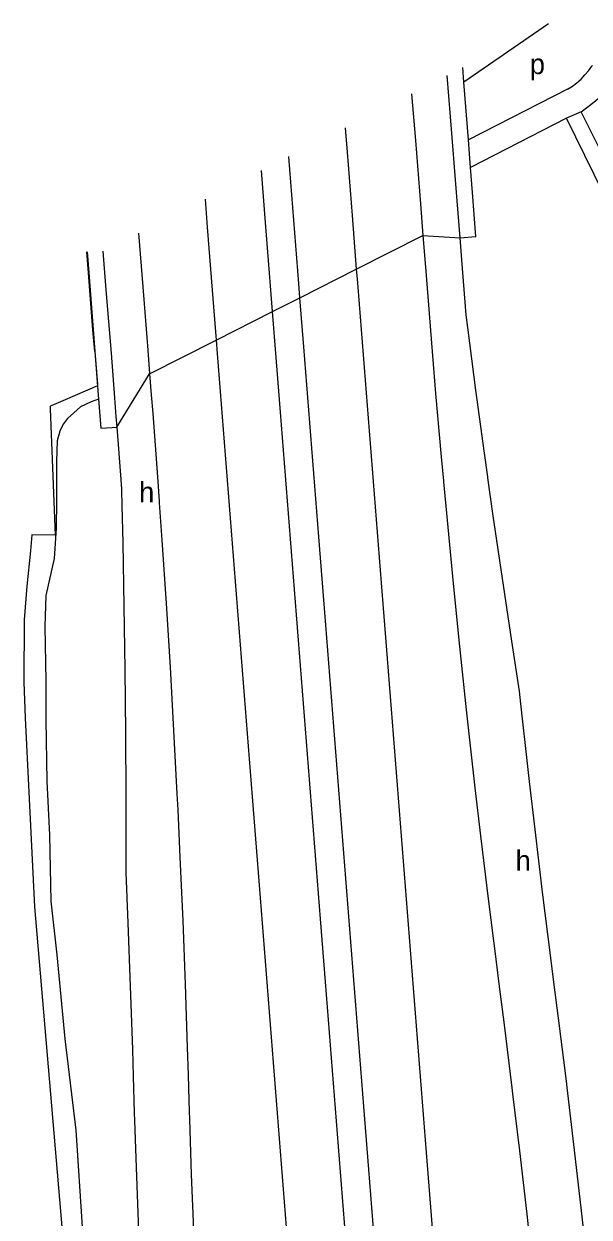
# Model space of a CAD drawing. Extents: x 157794 to 159375, y 380877 to 382306.
# Drawn here: x 157819.1 to 157930.4, y 381260.8 to 381495.7 of the extents above; entities that cross this region are included whole.
import ezdxf

# ---------------------------------------------------------------- set-up
doc = ezdxf.new("R2010")
doc.units = 0
for name, color, linetype in [('BLT_Basislijn', 7, 'Continuous'), ('BLT_Centroide', 7, 'Continuous'), ('BLT_Gemeentegrens', 7, 'Continuous'), ('BLT_Vlakafsluiter', 7, 'Continuous')]:
    doc.layers.add(name, color=color, linetype=linetype)

msp = doc.modelspace()

# ---------------------------------------------------------------- linework, layer by layer
at = {"layer": 'BLT_Basislijn'}
for p, q in [((157926.16, 381482.84), (157906.62, 381472.85)), ((157928.82, 381478.37), (157925.97, 381477.12)), ((157941.55, 381452.87), (157928.82, 381478.37)), ((157925.97, 381477.12), (157907.04, 381467.45)), ((157884.54, 381447.4), (157897.66, 381454.03)), ((157831.56, 381450.81), (157831.88, 381446.71)), ((157868.05, 381439.07), (157873.45, 381441.79)), ((157832.7, 381435.5), (157832.75, 381435.52)), ((157843.84, 381426.83), (157856.96, 381433.46)), ((157833.04, 381431.21), (157833.08, 381431.23))]:
    msp.add_line(p, q, dxfattribs=at)
for points in [[(157922.42, 381495.71), (157905.74, 381484.26)], [(157905.74, 381484.26), (157905.52, 381487.09)], [(157926.16, 381482.84), (157927.09, 381483.44), (157927.97, 381484.11), (157928.81, 381484.85), (157929.58, 381485.64), (157930.3, 381486.48), (157930.96, 381487.38), (157931.03, 381487.49)], [(157928.82, 381478.37), (157931.33, 381480.26), (157932.2, 381481.01), (157933.01, 381481.82), (157933.77, 381482.69), (157934.46, 381483.61), (157935.09, 381484.57), (157935.65, 381485.58), (157936.14, 381486.62), (157936.21, 381486.78)], [(157904.97, 381453.59), (157904.39, 381460.86), (157903.41, 381473.32), (157902.44, 381485.52)], [(157906.62, 381472.85), (157905.74, 381484.26)], [(157895.45, 381481.96), (157896.18, 381472.75), (157897.17, 381460.29), (157897.66, 381454.03)], [(157882.34, 381475.27), (157882.72, 381470.43), (157883.71, 381457.96), (157884.54, 381447.4)], [(157951.29, 381444.28), (157949.71, 381444.16), (157947.76, 381444.27), (157943.92, 381445.59), (157940.99, 381447.89), (157939.52, 381449.69), (157938.6, 381451.33), (157925.97, 381477.12)], [(157907.04, 381467.45), (157906.62, 381472.85)], [(157873.45, 381441.79), (157873.23, 381444.6), (157872.24, 381457.06), (157871.26, 381469.52), (157871.25, 381469.61)], [(157868.05, 381439.07), (157867.65, 381444.15), (157866.66, 381456.62), (157865.85, 381466.86)], [(157907.42, 381462.51), (157907.04, 381467.45)], [(157854.76, 381461.2), (157855.2, 381455.71), (157856.18, 381443.25), (157856.96, 381433.46)], [(157904.97, 381453.59), (157908.09, 381453.83), (157907.42, 381462.51)], [(157841.65, 381454.52), (157842.49, 381443.91), (157843.47, 381431.45), (157843.84, 381426.83)], [(157897.66, 381454.03), (157898.15, 381447.83), (157898.81, 381439.51), (157899.14, 381435.37), (157900.17, 381422.91), (157901.26, 381410.45), (157901.69, 381405.74), (157901.71, 381405.56), (157902.41, 381398), (157903.62, 381385.56), (157904.88, 381373.12), (157906.21, 381360.69), (157907.58, 381348.26), (157907.92, 381345.31), (157909.02, 381335.84), (157910.52, 381323.43), (157912.07, 381311.03), (157912.69, 381306.21), (157913.65, 381298.63), (157915.19, 381286.23), (157915.34, 381285.03), (157916.67, 381273.82), (157918.1, 381261.4), (157919.46, 381248.98)], [(157930.2, 381250.13), (157928.83, 381262.6), (157927.4, 381275.07), (157926.06, 381286.33), (157925.91, 381287.53), (157924.37, 381299.98), (157923.4, 381307.59), (157922.78, 381312.39), (157921.24, 381324.75), (157919.75, 381337.11), (157918.65, 381346.54), (157918.32, 381349.48), (157916.94, 381361.86), (157916.67, 381364.33), (157915.16, 381374.19), (157913.31, 381386.52), (157911.52, 381398.86), (157910.46, 381406.36), (157910.43, 381406.54), (157909.78, 381411.22), (157908.1, 381423.58), (157906.48, 381435.96), (157906.17, 381438.43), (157906.04, 381440.08), (157905.38, 381448.4), (157904.97, 381453.59)], [(157834.66, 381450.95), (157835.26, 381443.34), (157836.25, 381430.88), (157836.94, 381422.08), (157837.23, 381418.42), (157837.38, 381416.33)], [(157831.82, 381446.68), (157831.88, 381446.71)], [(157831.88, 381446.71), (157832.75, 381435.52)], [(157884.54, 381447.4), (157884.69, 381445.5), (157885.68, 381433.04), (157886.66, 381420.58), (157887.65, 381408.12), (157888.63, 381395.66), (157889.62, 381383.2), (157890.6, 381370.74), (157891.59, 381358.28), (157892.58, 381345.81), (157893.56, 381333.35), (157894.55, 381320.89), (157895.53, 381308.43), (157896.52, 381295.97), (157897.5, 381283.51), (157898.49, 381271.05), (157899.47, 381258.59)], [(157888.01, 381257.68), (157887.02, 381270.14), (157886.04, 381282.6), (157885.05, 381295.06), (157884.07, 381307.52), (157883.08, 381319.99), (157882.1, 381332.45), (157881.11, 381344.91), (157880.13, 381357.37), (157879.14, 381369.83), (157878.16, 381382.29), (157877.17, 381394.75), (157876.18, 381407.21), (157875.2, 381419.67), (157874.21, 381432.14), (157873.45, 381441.79)], [(157882.43, 381257.24), (157881.44, 381269.7), (157880.46, 381282.16), (157879.47, 381294.62), (157878.48, 381307.08), (157877.5, 381319.54), (157876.51, 381332.01), (157875.53, 381344.47), (157874.54, 381356.93), (157873.56, 381369.39), (157872.57, 381381.85), (157871.59, 381394.31), (157870.6, 381406.77), (157869.62, 381419.23), (157868.63, 381431.69), (157868.05, 381439.07)], [(157832.75, 381435.52), (157833.08, 381431.23)], [(157856.96, 381433.46), (157857.17, 381430.79), (157858.15, 381418.33), (157859.14, 381405.87), (157860.12, 381393.4), (157861.11, 381380.94), (157862.09, 381368.48), (157863.08, 381356.02), (157864.06, 381343.56), (157865.05, 381331.1), (157866.04, 381318.64), (157867.02, 381306.18), (157868.01, 381293.72), (157868.99, 381281.25), (157869.98, 381268.79), (157870.96, 381256.33)], [(157833.08, 381431.23), (157833.81, 381421.79)], [(157843.84, 381426.83), (157844.17, 381422.65), (157844.46, 381418.99), (157845.4, 381406.52), (157845.74, 381401.75), (157845.76, 381401.4), (157846.28, 381394.05), (157847.1, 381381.57), (157847.87, 381369.09), (157848.58, 381356.61), (157849.23, 381344.13), (157849.38, 381340.96), (157849.82, 381331.64), (157850.36, 381319.15), (157850.83, 381306.66), (157851.25, 381294.16), (157851.41, 381288.82), (157851.57, 381283.73)], [(157833.81, 381421.79), (157832.33, 381421.27), (157830.27, 381420.29), (157828.92, 381419.15), (157827.69, 381418.01), (157826.86, 381416.87), (157826.18, 381415.49), (157825.63, 381413.61), (157825.54, 381409.52), (157825.53, 381401.81), (157825.42, 381396.41), (157825.06, 381390.44)], [(157833.81, 381421.79), (157834.25, 381416.09), (157836.48, 381416.26)], [(157836.48, 381416.26), (157837.38, 381416.33)], [(157837.38, 381416.33), (157838.16, 381405.99), (157838.3, 381404.1)], [(157838.3, 381404.1), (157838.34, 381403.5), (157838.4, 381401.23), (157838.41, 381400.88), (157838.57, 381393.52), (157838.8, 381381.04), (157838.98, 381368.57), (157839.09, 381356.1), (157839.15, 381343.62), (157839.16, 381340.46), (157839.15, 381331.16), (157839.14, 381328.66), (157839.56, 381318.71), (157840.04, 381306.27), (157840.46, 381293.82), (157840.62, 381288.51), (157840.84, 381281.32), (157840.89, 381279.75), (157841.27, 381268.78), (157841.76, 381256.24), (157842.11, 381243.7), (157842.3, 381231.14), (157842.32, 381219.08)], [(157825.06, 381390.44), (157823.42, 381383.18), (157823.24, 381377.09), (157823.39, 381366.32), (157823.39, 381358.68), (157823.61, 381346.59), (157824.14, 381335.97), (157824.42, 381322.97), (157825.55, 381312.41), (157827.15, 381295.92), (157829.34, 381277.88), (157830.56, 381258.85), (157831.69, 381241.7), (157832.65, 381228.56), (157833.59, 381216.13), (157833.7, 381206.77), (157833.46, 381196.16)], [(157851.57, 381283.73), (157851.63, 381281.67), (157851.68, 381280.1), (157852.06, 381269.18), (157852.55, 381256.69), (157853.09, 381244.2), (157853.69, 381231.72), (157854.35, 381219.24)]]:
    msp.add_lwpolyline(points, dxfattribs=at)
at = {"layer": 'BLT_Gemeentegrens'}
for points in [[(157831.82, 381446.68), (157831.49, 381450.81)], [(157832.7, 381435.5), (157831.82, 381446.68)], [(157833.04, 381431.21), (157832.7, 381435.5)], [(157833.04, 381431.21), (157833.56, 381424.71), (157833.58, 381424.44), (157827.19, 381421.69), (157824.95, 381420.73), (157824.25, 381420.43), (157824.27, 381419.93), (157825.28, 381395.03), (157820.63, 381395.14), (157820.38, 381391.97), (157819.67, 381385), (157819.16, 381378.36), (157819.09, 381366.09), (157819.33, 381359.06), (157821.16, 381321.86), (157827.04, 381253.5)]]:
    msp.add_lwpolyline(points, dxfattribs=at)
at = {"layer": 'BLT_Vlakafsluiter'}
for p, q in [((157897.66, 381454.03), (157904.97, 381453.59)), ((157873.45, 381441.79), (157884.54, 381447.4)), ((157856.96, 381433.46), (157868.05, 381439.07)), ((157837.38, 381416.33), (157843.84, 381426.83))]:
    msp.add_line(p, q, dxfattribs=at)

# ---------------------------------------------------------------- texts
at = {"layer": 'BLT_Centroide'}
for s, p in [('p', (157918.72, 381485.8)), ('h', (157841.8, 381401.51)), ('h', (157915.92, 381328.97))]:
    msp.add_text(s, height=4, dxfattribs=at).set_placement(p)

doc.saveas('drawing.dxf')
